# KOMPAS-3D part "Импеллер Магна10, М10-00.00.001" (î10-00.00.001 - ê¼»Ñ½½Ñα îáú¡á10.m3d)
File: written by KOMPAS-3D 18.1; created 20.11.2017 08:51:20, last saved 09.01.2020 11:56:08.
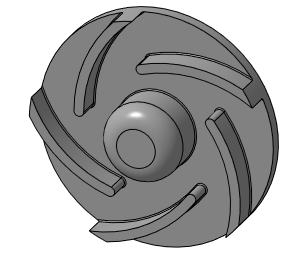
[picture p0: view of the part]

Document properties: Полное имя файла: D:\Magna\Магна Ins\Магна ins 10\М10-00.00.000\3Д\М10-00.00.001 - Импеллер Магна10.m3d

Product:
- Part/product: Импеллер Магна10  | designation М10-00.00.001
    Масса: 0.169927
    Раздел спецификации: Детали
    Форматы листов документа: A3
    source file: М10-00.00.001 - Импеллер Магна10.cdw
  - Component: Импеллер Магна10  | designation М10-00.00.001  | Масса: 0.169925; Раздел спецификации: Детали; Форматы листов документа: A3; source file: М10-00.00.001 - Импеллер Магна10.cdw
  - Body: Тело 1
      Масса: 0.138344
  - Component [billet]: Закладная М10  | designation М10-00.00.005
      Материал: Сталь 12Х18Н10Т ГОСТ 5632-72 (density 7900 kg/m3)
      Масса: 0.0315836
      Раздел спецификации: Детали
      Форматы листов документа: A4
      Плотность: 7900
      source file: М10-00.00.005 - Закладная М10.cdw, М10-00.00.005 - Закладная М10.m3d
  - Component [billet]: Закладная М10  | designation М10-00.00.005  | Материал: Сталь 12Х18Н10Т ГОСТ 5632-72 (density 7900 kg/m3); Раздел спецификации: Детали; Форматы листов документа: A4; Плотность: 7900; source file: М10-00.00.005 - Закладная М10.cdw, М10-00.00.005 - Закладная М10.m3d

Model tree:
1. Операция без истории:1
2. Булева операция:1
3. Отверстие:2  (with: Операция выдавливания:1)
     Глубина выреза = 21; Диаметр отверстия = 8.3762; Угол конуса торца = 118
4. M10  (with: Операция выдавливания:1)  (labels: cil0_24705-2004 coarse)
     Длина резьбы = 18; Шаг резьбы = 1.5; Номинальный диаметр резьбы = 10
5. Смещенная плоскость:1  (with: Операция без истории:1, Операция выдавливания:1, Вырезать элемент выдавливания:1)  (labels: Сталь 12Х18Н10Т ГОСТ 5632-72)
     Расстояние = -15

Referenced files in D:\Magna\Магна Ins\Магна ins 10\М10-00.00.000\3Д\: М10-00.00.001 - Импеллер Магна10.cdw, М10-00.00.005 - Закладная М10.m3d
Referenced files in Z:\Магна\Магна Ins\Магна ins 10\М10-00.00.000\3Д\: М10-00.00.005 - Закладная М10.m3d
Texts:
  (Заготовка для М10-00.00.001)
  Закладная М10 / (Заготовка для М10-00.00.001)
  М10-00.00.005 Закладная М10 (1)
  М10-00.00.005 Закладная М10 (2)

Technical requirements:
  Gost Type A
